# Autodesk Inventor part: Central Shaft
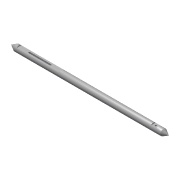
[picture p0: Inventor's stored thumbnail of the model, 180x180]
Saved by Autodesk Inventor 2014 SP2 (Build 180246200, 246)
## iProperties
Created: 2015-04
Part Number: Central Shaft
Material: Steel
Document SubType Name: Modeling
Designer: SFC
Density: 7.85 g/cm^3
Appearance: Steel
Mass: 1824.89 g
Surface Area: 455.739 cm^2
Volume: 232.47 cm^3
Author: SFC
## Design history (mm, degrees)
sketch "Sketch1"
  geometry: L1 (-300, 0)-(300, 0); L2 (279.215, 12)-(-279.215, 12); L3 (279.215, 12)-(300, 0); L4 (-279.215, 12)-(-300, 0); 2 further points
  constraints: 8 end point, 2 midpoint, 1 coincident, 1 horizontal, 1 parallel
  dimensions: "d0" = 24 diameter of L2 L1; "d2" = 600 distance of L1.end L1.start; "d3" = 30 deg angle of L2 L4; "d4" = 30 deg angle of L2 L3 (= d3)
revolve "Revolution1" sketch "Sketch1" stored, may be unused: angle "d6" = 90 deg
sketch "Sketch2"
  geometry: L1 (-260, 12)-(-240, 12); L2 (-240, 12)-(-240, 8); L3 (-240, 8)-(-260, 8); L4 (-260, 8)-(-260, 12); L5 (-260, -12)-(-240, -12); L6 (-240, -12)-(-240, -8); L7 (-240, -8)-(-260, -8); L8 (-260, -8)-(-260, -12); L9 (110, 12)-(270, 12); L10 (270, 12)-(270, 8); L11 (270, 8)-(110, 8); L12 (110, 8)-(110, 12); L13 (110, -12)-(270, -12); L14 (270, -12)-(270, -8); L15 (270, -8)-(110, -8); L16 (110, -8)-(110, -12); L17 (279.215, 12)-(-279.215, 12) reference; L18 (279.215, -12)-(-279.215, -12) reference; 1 further point
  constraints: 32 end point, 11 collinear, 8 parallel, 4 horizontal, 4 perpendicular
  dimensions: "d7" = 16 distance between parallel lines of L7 L3; "d8" = 20 distance of L1.start L1.end; "d9" = 160 distance of L9.start L9.end; "d10" = 350 distance between parallel lines of L12 L2; "d11" = 240 horizontal distance of point (0, 0) L5.end
extrude "Extrusion1" cut sketch "Sketch2" stored distance "d12" = 10; taper "d13" = 0 deg
sketch "Sketch3"
  geometry: L1 (0, 0)-(160, 0) reference; L2 (510, 0)-(530, 0) reference; L3 (0, 0)-(0, -17.889) reference; L4 (40, -8.944)-(120, -8.944); L5 (40, -5.944)-(120, -5.944); L6 (120, -11.944)-(40, -11.944); C1 r 3 at (520, -8.944); A1 r 3 centre (40, -8.944) between (40, -5.944) and (40, -11.944); A2 r 3 centre (120, -8.944) between (120, -11.944) and (120, -5.944); 7 further points
  constraints: 8 end point, 6 midpoint, 4 point on circle, 4 tangent, 3 centre point, 2 horizontal alignment, 2 parallel, 2 vertical alignment
  dimensions: "d14" = 6 diameter of C1; "d15" = 80 distance of L5.start L5.end; "d19" = 6 distance between parallel lines of L6 L5
extrude "Extrusion2" cut sketch "Sketch3" stored distance "d20" = 10; taper "d21" = 0 deg
body "Solid1"
